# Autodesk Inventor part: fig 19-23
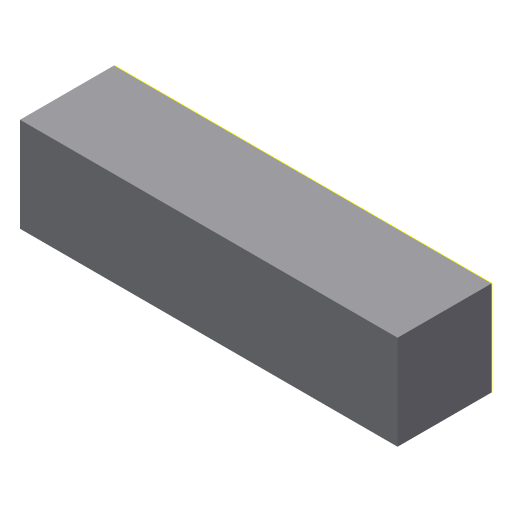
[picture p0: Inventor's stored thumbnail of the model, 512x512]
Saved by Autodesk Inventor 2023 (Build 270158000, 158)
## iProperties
Created: 2013-07
Part Number: fig 19-23
Material: Generic
Document SubType Name: Modeling
Designer: CADCIM
Density: 1 g/cm^3
Appearance: Default
Author: CADCIM
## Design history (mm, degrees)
sketch "Sketch1"
  geometry: L1 (-20, 5)-(20, 5); L2 (20, 5)-(20, -5); L3 (20, -5)-(-20, -5); L4 (-20, -5)-(-20, 5); L5 (-20, 5)-(20, -5); L6 (20, 5)-(-20, -5); 1 further point
  constraints: 12 end point, 2 midpoint, 2 parallel, 1 horizontal, 1 perpendicular
  dimensions: "d0" = 40 distance of L2.end L3.end; "d1" = 10 distance of L1.end L2.end
extrude "Extrusion1" new body sketch "Sketch1" distance "d2" = 10; taper "d3" = 0 deg
sketch "Sketch2"
  geometry: L1 (0, 0)-(40, 0) reference; L2 (0, 0)-(0, -10) reference; L3 (40, -10)-(0, -10) reference; L4 (40, 0)-(40, -10) reference; 2 further points
body "Solid1"
